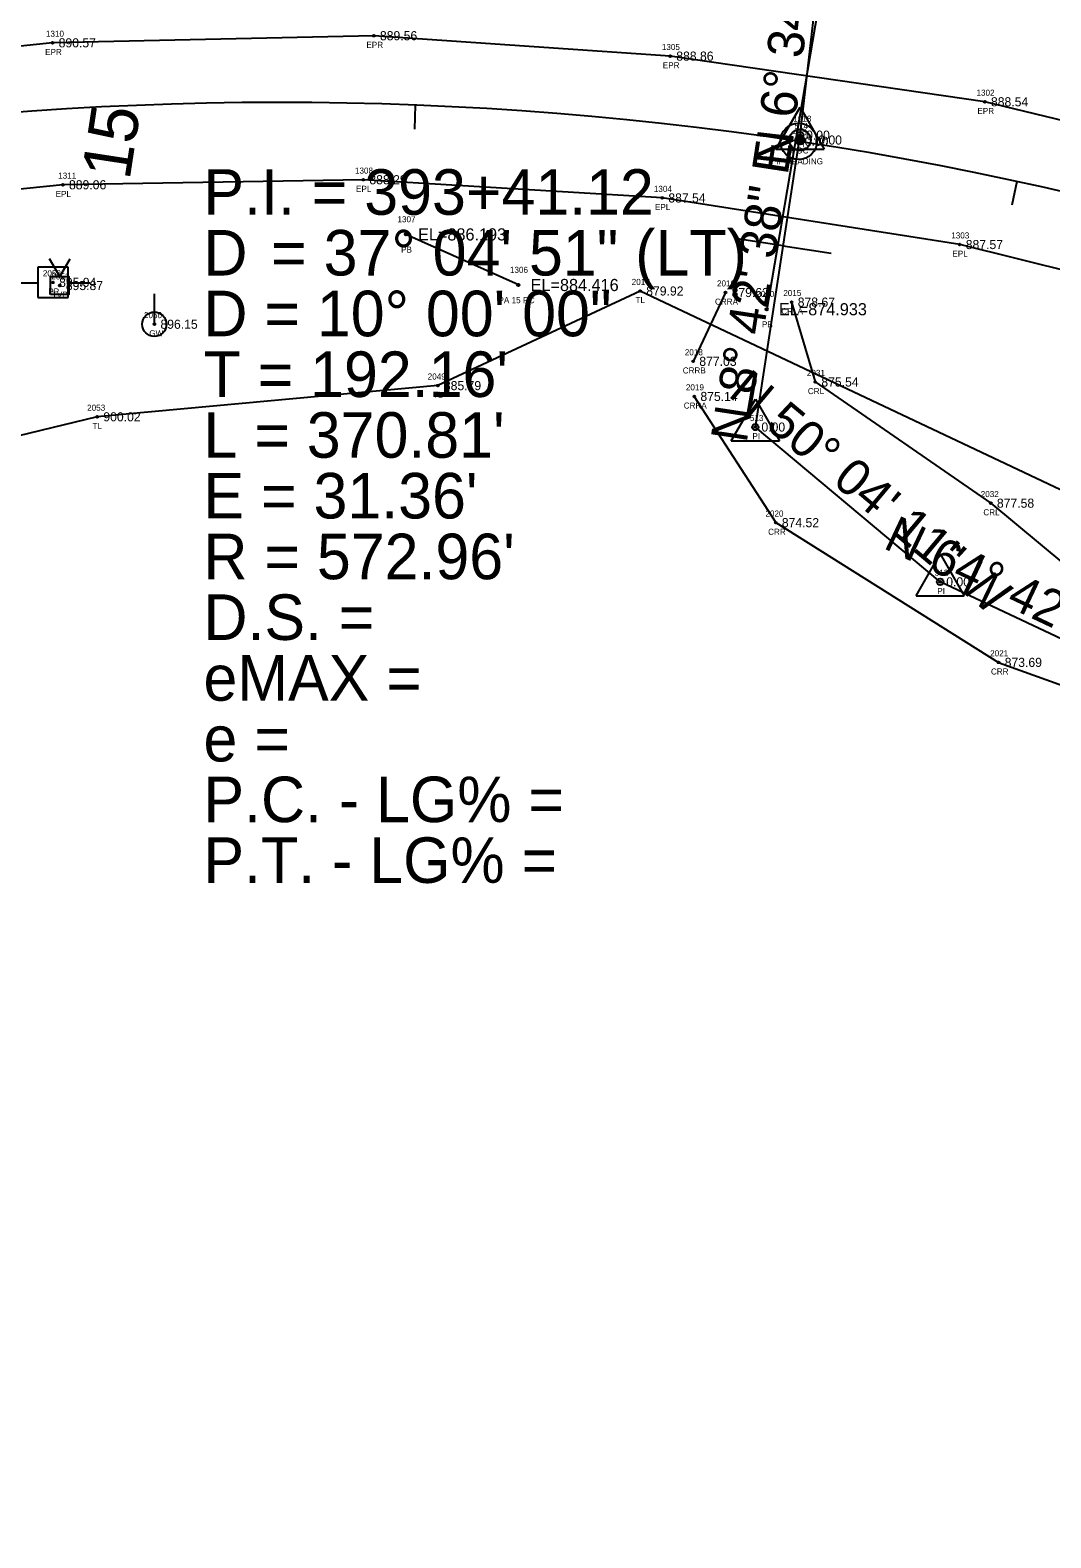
# Model space of a CAD drawing. Extents: x 1448136 to 1453623, y 1125056 to 1128842.
# Drawn here: x 1449083.5 to 1449251.5, y 1126696.2 to 1126944.4 of the extents above; entities that cross this region are included whole.
import ezdxf

# ---------------------------------------------------------------- set-up
doc = ezdxf.new("R2010")
doc.units = 0
for name, color, linetype in [('RD_EX_DR_Pipe', 7, 'Continuous'), ('RD_EX_DR_Pipe_txCode', 7, 'Continuous'), ('RD_EX_DV_Prop_txCode', 7, 'Continuous'), ('RD_EX_DV_PropPin', 7, 'Continuous'), ('RD_EX_H2O', 7, 'Continuous'), ('RD_EX_H2O_txCode', 7, 'Continuous'), ('RD_EX_Road', 7, 'Continuous'), ('RD_EX_Road_txCode', 7, 'Continuous'), ('RD_EX_TX_DV_Prop_ELEV', 7, 'Continuous'), ('RD_EX_TX_H2O_ELEV', 7, 'Continuous'), ('RD_EX_TX_Road_ELEV', 7, 'Continuous'), ('RD_EX_TX_UT_ELEV', 7, 'Continuous'), ('RD_EX_TX_VEG_ELEV', 7, 'Continuous'), ('RD_EX_UT', 7, 'Continuous'), ('RD_EX_UT_txCode', 7, 'Continuous'), ('RD_EX_VEG', 7, 'Continuous'), ('RD_EX_VEG_txCode', 7, 'Continuous'), ('RD_HC_Cl', 7, 'Continuous'), ('RD_HC_Data', 7, 'Continuous'), ('RD_HC_Data_Tic', 7, 'Continuous'), ('RD_HC_Survey_ELEV', 7, 'Continuous'), ('RD_HC_TX_Sta50', 7, 'Continuous'), ('RD_HC_txCode', 7, 'Continuous'), ('RD_SMD_Locator', 7, 'Continuous'), ('RD_TX_Pipe_ElevEX', 7, 'Continuous')]:
    doc.layers.add(name, color=color, linetype=linetype)

msp = doc.modelspace()

# ---------------------------------------------------------------- linework, layer by layer
at = {"layer": 'RD_EX_DR_Pipe'}
for p, q in [((1449214.42, 1126955.17), (1449204.75, 1126898.45)), ((1449163.87, 1126902.44), (1449145.33, 1126910.77))]:
    msp.add_line(p, q, dxfattribs=at)
at = {"layer": 'RD_EX_DV_PropPin'}
for p, q in [((1449209.5, 1126926.11), (1449209.5, 1126926.5)), ((1449209.54, 1126926.01), (1449209.54, 1126926.61)), ((1449209.57, 1126925.94), (1449209.57, 1126926.68)), ((1449209.61, 1126925.88), (1449209.61, 1126926.74)), ((1449209.64, 1126925.83), (1449209.64, 1126926.78)), ((1449209.68, 1126925.79), (1449209.68, 1126926.82)), ((1449209.71, 1126925.76), (1449209.71, 1126926.86)), ((1449209.75, 1126925.73), (1449209.75, 1126926.89)), ((1449209.78, 1126925.7), (1449209.78, 1126926.92)), ((1449209.82, 1126925.67), (1449209.82, 1126926.94)), ((1449209.85, 1126925.65), (1449209.85, 1126926.96)), ((1449209.89, 1126925.63), (1449209.89, 1126926.98)), ((1449209.92, 1126925.62), (1449209.92, 1126927)), ((1449209.96, 1126925.6), (1449209.96, 1126927.02)), ((1449209.99, 1126925.59), (1449209.99, 1126927.03)), ((1449210.03, 1126925.58), (1449210.03, 1126927.04)), ((1449210.06, 1126925.57), (1449210.06, 1126927.05)), ((1449210.1, 1126925.56), (1449210.1, 1126927.06)), ((1449210.13, 1126925.55), (1449210.13, 1126927.06)), ((1449210.17, 1126925.55), (1449210.17, 1126927.07)), ((1449210.2, 1126925.55), (1449210.2, 1126927.07)), ((1449210.24, 1126925.55), (1449210.24, 1126927.07)), ((1449210.27, 1126925.55), (1449210.27, 1126927.07)), ((1449210.31, 1126925.55), (1449210.31, 1126927.07)), ((1449210.34, 1126925.55), (1449210.34, 1126927.06)), ((1449210.38, 1126925.56), (1449210.38, 1126927.06)), ((1449210.41, 1126925.57), (1449210.41, 1126927.05)), ((1449210.45, 1126925.58), (1449210.45, 1126927.04)), ((1449210.48, 1126925.59), (1449210.48, 1126927.03)), ((1449210.52, 1126925.6), (1449210.52, 1126927.02)), ((1449210.55, 1126925.62), (1449210.55, 1126927)), ((1449210.59, 1126925.63), (1449210.59, 1126926.98)), ((1449210.62, 1126925.65), (1449210.62, 1126926.96)), ((1449210.66, 1126925.67), (1449210.66, 1126926.94)), ((1449210.69, 1126925.7), (1449210.69, 1126926.92)), ((1449210.73, 1126925.73), (1449210.73, 1126926.89)), ((1449210.76, 1126925.76), (1449210.76, 1126926.86)), ((1449210.8, 1126925.79), (1449210.8, 1126926.82)), ((1449210.83, 1126925.83), (1449210.83, 1126926.78)), ((1449210.87, 1126925.88), (1449210.87, 1126926.74)), ((1449210.9, 1126925.94), (1449210.9, 1126926.68)), ((1449210.94, 1126926.01), (1449210.94, 1126926.61)), ((1449210.97, 1126926.11), (1449210.97, 1126926.5))]:
    msp.add_line(p, q, dxfattribs=at)
for radius in [1.75, 0.761]:
    msp.add_circle((1449210.24, 1126926.31), radius, dxfattribs=at)
at = {"layer": 'RD_EX_H2O'}
msp.add_line((1449197.97, 1126901.2), (1449192.65, 1126889.87), dxfattribs=at)
for points in [[(1449208.86, 1126899.62), (1449212.75, 1126886.47), (1449241.66, 1126866.52), (1449270.24, 1126842.78), (1449281.51, 1126821.49), (1449278.98, 1126797.31), (1449268.67, 1126769.23), (1449277.63, 1126757.82), (1449294.57, 1126788.83), (1449310.34, 1126786.1), (1449345.24, 1126766.4), (1449396.68, 1126720.02), (1449415.79, 1126685.66), (1449412.26, 1126639.96), (1449451.97, 1126613.73)], [(1449192.83, 1126884.09), (1449206.24, 1126863.31), (1449242.94, 1126840.31), (1449264.95, 1126832.37), (1449267.51, 1126794.69), (1449256.98, 1126771.22), (1449273.47, 1126746.24), (1449292.55, 1126757.46), (1449299.74, 1126772.91), (1449318.83, 1126758.93), (1449342.3, 1126750.49), (1449381.5, 1126709), (1449403.98, 1126679.1), (1449387.22, 1126637.03), (1449449.83, 1126593.98)]]:
    msp.add_lwpolyline(points, dxfattribs=at)
at = {"layer": 'RD_EX_Road'}
for points in [[(1449482.54, 1126860.68), (1449432.31, 1126877.02), (1449388.08, 1126891.1), (1449338.36, 1126907.04), (1449288.58, 1126921), (1449240.68, 1126932.6), (1449188.86, 1126940.12), (1449140.06, 1126943.48), (1449087.15, 1126942.31), (1449035.96, 1126936.97), (1449031.74, 1126936.28), (1449027.6, 1126937.81), (1449023.03, 1126937.4), (1448974.11, 1126927.16), (1448972.81, 1126925.93), (1448941.11, 1126916.24), (1448934.6, 1126912.22), (1448888.05, 1126895.64)], [(1449474.36, 1126838.35), (1449426.72, 1126853.6), (1449379.49, 1126868.74), (1449332.07, 1126883.87), (1449284.48, 1126897.19), (1449236.53, 1126909.1), (1449187.55, 1126916.77), (1449138.32, 1126919.77), (1449088.85, 1126918.94), (1449039.71, 1126913.91), (1448991.01, 1126903.73), (1448942.83, 1126890.02), (1448896.24, 1126874.12)]]:
    msp.add_lwpolyline(points, dxfattribs=at)
at = {"layer": 'RD_EX_UT'}
for p, q in [((1449089.71, 1126905.38), (1449084.71, 1126905.38)), ((1449084.71, 1126905.38), (1449084.71, 1126900.38)), ((1449088.33, 1126903.85), (1449086.66, 1126906.74)), ((1449088.33, 1126903.85), (1449090.07, 1126906.74)), ((1449089.71, 1126900.38), (1449089.71, 1126905.38)), ((1449081.28, 1126902.82), (1449084.75, 1126902.82)), ((1449089.64, 1126902.82), (1449093.28, 1126902.82)), ((1449084.71, 1126900.38), (1449089.71, 1126900.38)), ((1449103.91, 1126895.98), (1449103.91, 1126900.98))]:
    msp.add_line(p, q, dxfattribs=at)
msp.add_lwpolyline([(1449086.83, 1126900.85), (1449086.83, 1126903.85), (1449089.83, 1126903.85), (1449089.83, 1126900.85)], close=True, dxfattribs=at)
msp.add_circle((1449103.91, 1126895.98), 2, dxfattribs=at)
at = {"layer": 'RD_EX_VEG'}
msp.add_lwpolyline([(1449580.16, 1126756.85), (1449515.49, 1126772.44), (1449452.16, 1126796.48), (1449411.7, 1126813.35), (1449361.89, 1126826.23), (1449322.6, 1126840.71), (1449267.19, 1126862.08), (1449183.91, 1126901.45), (1449150.59, 1126885.87), (1449094.51, 1126880.74), (1449046.23, 1126869.03), (1449021.78, 1126857.03), (1449018.91, 1126811.39)], dxfattribs=at)
at = {"layer": 'RD_HC_Cl'}
for p, q in [((1449210.24, 1126927.11), (1449215.21, 1126970.22)), ((1449202.88, 1126879.05), (1449210.24, 1126927.11)), ((1449233.32, 1126853.57), (1449202.88, 1126879.05)), ((1449266.92, 1126837.7), (1449233.32, 1126853.57))]:
    msp.add_line(p, q, dxfattribs=at)
msp.add_arc((1449124.53, 1126359.54), 572.96, 72.66042, 109.74133, dxfattribs=at)
at = {"layer": 'RD_HC_Data'}
for p, q in [((1449206.27, 1126924.82), (1449210.24, 1126931.7)), ((1449210.24, 1126931.7), (1449214.21, 1126924.82)), ((1449206.27, 1126924.82), (1449214.21, 1126924.82)), ((1449198.9, 1126876.76), (1449202.88, 1126883.64)), ((1449202.88, 1126883.64), (1449206.85, 1126876.76)), ((1449198.9, 1126876.76), (1449206.85, 1126876.76)), ((1449229.34, 1126851.28), (1449233.32, 1126858.16)), ((1449233.32, 1126858.16), (1449237.29, 1126851.28)), ((1449229.34, 1126851.28), (1449237.29, 1126851.28))]:
    msp.add_line(p, q, dxfattribs=at)
for centre, radius in [((1449210, 1126926.09), 3), ((1449210.24, 1126927.11), 0.529), ((1449210, 1126926.09), 0.282), ((1449202.88, 1126879.05), 0.529), ((1449233.32, 1126853.57), 0.529)]:
    msp.add_circle(centre, radius, dxfattribs=at)
at = {"layer": 'RD_HC_Data_Tic'}
for p, q in [((1449146.88, 1126932.07), (1449146.73, 1126928.07)), ((1449245.96, 1126919.49), (1449245.11, 1126915.58)), ((1449207.45, 1126908.9), (1449199.54, 1126910.11)), ((1449207.45, 1126908.9), (1449215.36, 1126907.69))]:
    msp.add_line(p, q, dxfattribs=at)
at = {"layer": 'RD_SMD_Locator'}
for centre, radius in [((1449087.15, 1126942.31), 0.15), ((1449140.06, 1126943.48), 0.15), ((1449188.86, 1126940.12), 0.15), ((1449240.68, 1126932.6), 0.15), ((1449210.24, 1126927.11), 0.15), ((1449210, 1126926.09), 0.15), ((1449210.24, 1126926.31), 0.15), ((1449138.32, 1126919.77), 0.15), ((1449088.85, 1126918.94), 0.15), ((1449187.55, 1126916.77), 0.15), ((1449145.33, 1126910.77), 0.2), ((1449236.53, 1126909.1), 0.15), ((1449087.22, 1126902.87), 0.15), ((1449088.33, 1126902.35), 0.15), ((1449163.87, 1126902.44), 0.2), ((1449183.91, 1126901.45), 0.15), ((1449197.97, 1126901.2), 0.15), ((1449204.75, 1126898.45), 0.2), ((1449208.86, 1126899.62), 0.15), ((1449103.91, 1126895.98), 0.15), ((1449192.65, 1126889.87), 0.15), ((1449150.59, 1126885.87), 0.15), ((1449212.75, 1126886.47), 0.15), ((1449192.83, 1126884.09), 0.15), ((1449094.51, 1126880.74), 0.15), ((1449202.88, 1126879.05), 0.15), ((1449241.66, 1126866.52), 0.15), ((1449206.24, 1126863.31), 0.15), ((1449233.32, 1126853.57), 0.15), ((1449242.94, 1126840.31), 0.15)]:
    msp.add_circle(centre, radius, dxfattribs=at)

# ---------------------------------------------------------------- texts
at = {"layer": 'RD_EX_DR_Pipe_txCode'}
for s, p in [('1307', (1449143.94, 1126912.77)), ('PB', (1449144.55, 1126907.77)), ('1306', (1449162.46, 1126904.44)), ('PA 15 RC', (1449160.58, 1126899.44)), ('2030', (1449203.04, 1126900.45)), ('PB', (1449203.97, 1126895.45))]:
    msp.add_text(s, height=1, dxfattribs=at).set_placement(p)
at = {"layer": 'RD_EX_DV_Prop_txCode'}
for s, p in [('1018', (1449209.14, 1126929.31)), ('IP READING', (1449206.3, 1126922.31))]:
    msp.add_text(s, height=1, dxfattribs=at).set_placement(p)
at = {"layer": 'RD_EX_H2O_txCode'}
for s, p in [('2016', (1449196.56, 1126902.2)), ('CRRA', (1449196.23, 1126899.2)), ('2015', (1449207.48, 1126900.62)), ('CRLA', (1449207.15, 1126897.62)), ('2018', (1449191.26, 1126890.87)), ('CRRB', (1449190.92, 1126887.87)), ('2031', (1449211.37, 1126887.47)), ('2019', (1449191.44, 1126885.09)), ('CRL', (1449211.53, 1126884.47)), ('CRRA', (1449191.09, 1126882.09)), ('2032', (1449239.99, 1126867.52)), ('2020', (1449204.54, 1126864.31)), ('CRL', (1449240.43, 1126864.52)), ('CRR', (1449204.99, 1126861.31)), ('2021', (1449241.55, 1126841.31)), ('CRR', (1449241.68, 1126838.31))]:
    msp.add_text(s, height=1, dxfattribs=at).set_placement(p)
at = {"layer": 'RD_EX_Road_txCode'}
for s, p in [('1310', (1449086.05, 1126943.31)), ('EPR', (1449138.83, 1126941.48)), ('EPR', (1449085.92, 1126940.31)), ('1305', (1449187.48, 1126941.12)), ('EPR', (1449187.64, 1126938.12)), ('1302', (1449239.3, 1126933.6)), ('EPR', (1449239.45, 1126930.6)), ('1311', (1449088.07, 1126919.94)), ('1308', (1449136.94, 1126920.77)), ('EPL', (1449087.65, 1126916.94)), ('EPL', (1449137.12, 1126917.77)), ('1304', (1449186.16, 1126917.77)), ('EPL', (1449186.35, 1126914.77)), ('1303', (1449235.14, 1126910.1)), ('EPL', (1449235.32, 1126907.1))]:
    msp.add_text(s, height=1, dxfattribs=at).set_placement(p)
at = {"layer": 'RD_EX_TX_DV_Prop_ELEV'}
msp.add_text('0.00', height=1.5, dxfattribs=at).set_placement((1449213.24, 1126925.56))
at = {"layer": 'RD_EX_TX_H2O_ELEV'}
for s, p in [('879.62', (1449198.97, 1126900.45)), ('878.67', (1449209.86, 1126898.87)), ('877.03', (1449193.65, 1126889.12)), ('875.54', (1449213.75, 1126885.72)), ('875.14', (1449193.83, 1126883.34)), ('877.58', (1449242.66, 1126865.77)), ('874.52', (1449207.24, 1126862.56)), ('873.69', (1449243.94, 1126839.56))]:
    msp.add_text(s, height=1.5, dxfattribs=at).set_placement(p)
at = {"layer": 'RD_EX_TX_Road_ELEV'}
for s, p in [('890.57', (1449088.15, 1126941.56)), ('889.56', (1449141.06, 1126942.73)), ('888.86', (1449189.86, 1126939.37)), ('888.54', (1449241.68, 1126931.85)), ('888.29', (1449139.32, 1126919.02)), ('889.06', (1449089.85, 1126918.19)), ('887.54', (1449188.55, 1126916.02)), ('887.57', (1449237.53, 1126908.35))]:
    msp.add_text(s, height=1.5, dxfattribs=at).set_placement(p)
at = {"layer": 'RD_EX_TX_UT_ELEV'}
for s, p in [('895.87', (1449089.33, 1126901.6)), ('896.15', (1449104.91, 1126895.23))]:
    msp.add_text(s, height=1.5, dxfattribs=at).set_placement(p)
at = {"layer": 'RD_EX_TX_VEG_ELEV'}
for s, p in [('879.92', (1449184.91, 1126900.7)), ('885.79', (1449151.59, 1126885.12)), ('900.02', (1449095.51, 1126879.99))]:
    msp.add_text(s, height=1.5, dxfattribs=at).set_placement(p)
at = {"layer": 'RD_EX_UT_txCode'}
for s, p in [('2052', (1449085.55, 1126903.87)), ('2051', (1449086.94, 1126903.35)), ('PP', (1449086.44, 1126900.87)), ('TVP', (1449087.05, 1126900.35)), ('2050', (1449102.2, 1126896.98)), ('GW', (1449103.07, 1126893.98))]:
    msp.add_text(s, height=1, dxfattribs=at).set_placement(p)
at = {"layer": 'RD_EX_VEG_txCode'}
for s, p in [('2017', (1449182.52, 1126902.45)), ('TL', (1449183.14, 1126899.45)), ('2049', (1449148.92, 1126886.87)), ('2053', (1449092.84, 1126881.74)), ('TL', (1449149.82, 1126883.87)), ('TL', (1449093.74, 1126878.74))]:
    msp.add_text(s, height=1, dxfattribs=at).set_placement(p)
at = {"layer": 'RD_HC_Data'}
for s, rotation, p in [('N 6%%d 34\' 55" E', 83.4179, (1449208.62, 1126921.82)), ('N 8%%d 42\' 38" E', 81.2896, (1449201.44, 1126876.31)), ('N 50%%d 04\' 11" W', 320.0697, (1449198.21, 1126884.26)), ('N 64%%d 42\' 53" W', 334.7147, (1449223.74, 1126859.2))]:
    msp.add_text(s, height=6, rotation=rotation, dxfattribs=at).set_placement(p)
for s, p in [('P.I. = 393+41.12', (1449112, 1126914)), ('D', (1449112, 1126904)), ('    = 37%%d 04\' 51" (LT)', (1449112, 1126904)), ('D = 10%%d 00\' 00"', (1449112, 1126894)), ("T = 192.16'", (1449112, 1126884)), ("L = 370.81'", (1449112, 1126874)), ("E = 31.36'", (1449112, 1126864)), ("R = 572.96'", (1449112, 1126854)), ('D.S. = ', (1449112, 1126844)), ('eMAX = ', (1449112, 1126834)), ('e = ', (1449112, 1126824)), ('P.C. - LG% = ', (1449112, 1126814)), ('P.T. - LG% = ', (1449112, 1126804))]:
    msp.add_text(s, height=7.5, dxfattribs=at).set_placement(p)
at = {"layer": 'RD_HC_Survey_ELEV'}
for s, p in [('0.00', (1449211.24, 1126926.36)), ('0.00', (1449211, 1126925.34)), ('895.94', (1449088.22, 1126902.12)), ('0.00', (1449203.88, 1126878.3)), ('0.00', (1449234.32, 1126852.82))]:
    msp.add_text(s, height=1.5, dxfattribs=at).set_placement(p)
at = {"layer": 'RD_HC_TX_Sta50'}
msp.add_text('15', height=8, rotation=81.2896, dxfattribs=at).set_placement((1449099.82, 1126919.56))
at = {"layer": 'RD_HC_txCode'}
for s, p in [('415', (1449209.11, 1126927.09)), ('514', (1449209.34, 1126928.11)), ('POC', (1449208.74, 1126924.09)), ('PI', (1449209.77, 1126925.11)), ('513', (1449201.98, 1126880.05)), ('PI', (1449202.4, 1126877.05)), ('512', (1449232.42, 1126854.57)), ('PI', (1449232.84, 1126851.57))]:
    msp.add_text(s, height=1, dxfattribs=at).set_placement(p)
at = {"layer": 'RD_TX_Pipe_ElevEX'}
for s, p in [('EL=886.193', (1449147.33, 1126909.77)), ('EL=884.416', (1449165.87, 1126901.44)), ('EL=874.933', (1449206.75, 1126897.45))]:
    msp.add_text(s, height=2, dxfattribs=at).set_placement(p)

doc.saveas('drawing.dxf')
